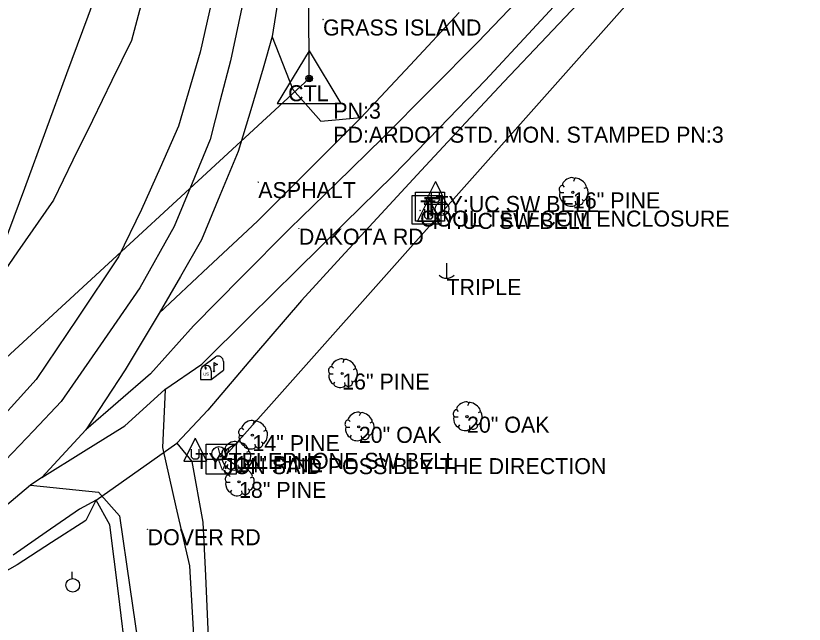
# Model space of a CAD drawing. Extents: x 1404740 to 1407214, y 1837339 to 1847120.
# Drawn here: x 1405702.8 to 1405948.8, y 1842254 to 1842443.8 of the extents above; entities that cross this region are included whole.
import ezdxf

# ---------------------------------------------------------------- set-up
doc = ezdxf.new("R2010")
doc.units = 0
for name, color, linetype in [('Ex_Major Contours', 7, 'Continuous'), ('S_BASELINE', 7, 'Continuous'), ('S_DITCHLINE', 7, 'Continuous'), ('S_EDGE_PAVEMENT', 7, 'Continuous'), ('S_GRAVEL_ROAD', 7, 'Continuous'), ('S_GUARDRAIL', 7, 'Continuous'), ('S_MAILBOX', 7, 'Continuous'), ('S_PAVEMENT_CROWN', 7, 'Continuous'), ('S_RDW_PT_SYM', 7, 'Continuous'), ('S_SECONDARY_CTL', 7, 'Continuous'), ('S_STREAM', 7, 'Continuous'), ('S_SURVEY_TEXT_ANNOT', 7, 'Continuous'), ('S_TELEPHONE_UTILITIES', 7, 'Continuous'), ('S_TREE', 7, 'Continuous'), ('S_TREE_ANNOT', 7, 'Continuous'), ('S_UNDERGROUND_CABLE', 7, 'Continuous'), ('S_UTILITY_POLE', 7, 'Continuous'), ('S_UTILITY_POLE_ANNOT', 7, 'Continuous'), ('S_UTL_PT_SYM', 7, 'Continuous'), ('S_WATER_UTILITIES', 7, 'Continuous'), ('S_WATER_UTILITIES_ANNOT', 7, 'Continuous')]:
    doc.layers.add(name, color=color, linetype=linetype)

msp = doc.modelspace()

# ---------------------------------------------------------------- linework, layer by layer
at = {"layer": 'Ex_Major Contours'}
msp.add_line((1405727.91, 1842292.7), (1405753.09, 1842310.52), dxfattribs=at)
at = {"layer": 'S_BASELINE'}
for p, q in [((1405794.37, 1842424.22), (1405791.52, 1843193.27)), ((1405509.79, 1842162.33), (1405794.37, 1842424.22))]:
    msp.add_line(p, q, dxfattribs=at)
at = {"layer": 'S_DITCHLINE'}
for points in [[(1405881.86, 1842451.53), (1405868.49, 1842437.35), (1405855.12, 1842423.17), (1405841.75, 1842408.98), (1405829.3, 1842395.5), (1405816.85, 1842382.01), (1405804.39, 1842368.53), (1405791.94, 1842355.04), (1405777.34, 1842337.89), (1405762.73, 1842320.75), (1405753.09, 1842310.52), (1405757.74, 1842304.75), (1405761.2, 1842285.84), (1405761.98, 1842269.07), (1405762.76, 1842252.3), (1405763.21, 1842237.38), (1405763.67, 1842222.46), (1405764.12, 1842207.55), (1405764.58, 1842192.63), (1405764.82, 1842178.84), (1405765.06, 1842165.05), (1405765.3, 1842151.25), (1405765.54, 1842137.46)], [(1405727.93, 1842292.76), (1405724.62, 1842286.36), (1405713.94, 1842279.47), (1405703.25, 1842272.57), (1405689.54, 1842264.87), (1405675.82, 1842257.16)], [(1405741, 1842131.76), (1405740.64, 1842146.6), (1405740.27, 1842161.44), (1405739.91, 1842176.28), (1405739.54, 1842191.12), (1405739.02, 1842203.87), (1405738.5, 1842216.62), (1405737.98, 1842229.38), (1405737.46, 1842242.13), (1405734.81, 1842263.59), (1405732.17, 1842285.05), (1405727.91, 1842292.7), (1405722.72, 1842289.93), (1405712.33, 1842282.74), (1405701.94, 1842275.54)]]:
    msp.add_lwpolyline(points, dxfattribs=at)
at = {"layer": 'S_EDGE_PAVEMENT'}
for points in [[(1405710.98, 1842299.77), (1405723.88, 1842307.83), (1405736.78, 1842315.88), (1405749.32, 1842327.2), (1405760.86, 1842335.14), (1405775.63, 1842349.74), (1405790.4, 1842364.34), (1405805.41, 1842379.1), (1405820.42, 1842393.87), (1405834.89, 1842408.8), (1405849.36, 1842423.73), (1405864, 1842439.51), (1405878.64, 1842455.29)], [(1405764.69, 1842451.92), (1405760.37, 1842432.46), (1405753.6, 1842409.33), (1405747.83, 1842396.33), (1405742.06, 1842383.33), (1405734.83, 1842368.65), (1405722.01, 1842349.47), (1405709.18, 1842330.3), (1405692.47, 1842312.03), (1405678.38, 1842299.61), (1405664.29, 1842287.19), (1405647.17, 1842275.28), (1405630.05, 1842263.37), (1405611.25, 1842251.51), (1405592.46, 1842239.65), (1405573.96, 1842228.7), (1405555.46, 1842217.75), (1405536.32, 1842206.98), (1405517.17, 1842196.2), (1405496.28, 1842183.85), (1405477.88, 1842173.74)], [(1405785.18, 1842452.58), (1405782.76, 1842437.37), (1405780.04, 1842427.45), (1405776.11, 1842414.48), (1405772.19, 1842401.51), (1405766.48, 1842387.73), (1405760.77, 1842373.95), (1405754.15, 1842362.5), (1405747.52, 1842351.05), (1405736.91, 1842333.36), (1405724.63, 1842314.65), (1405710.98, 1842299.77), (1405707.4, 1842297.35), (1405691.29, 1842283.83)], [(1405747.52, 1842351.05), (1405762.85, 1842365.38), (1405778.19, 1842379.72), (1405794.34, 1842395.85), (1405810.5, 1842411.98), (1405825.85, 1842428.4), (1405841.19, 1842444.82)], [(1405782.85, 1842437.26), (1405789.25, 1842420.8), (1405797.95, 1842410.9), (1405810.43, 1842412.04)]]:
    msp.add_lwpolyline(points, dxfattribs=at)
at = {"layer": 'S_GRAVEL_ROAD'}
for points in [[(1405749.39, 1842327.13), (1405748.57, 1842309.09), (1405752.79, 1842290.65), (1405757.02, 1842272.21), (1405758.2, 1842252.33), (1405759.38, 1842232.45), (1405760.37, 1842210.37), (1405761.35, 1842188.29), (1405761.66, 1842174.26), (1405761.97, 1842160.22), (1405762.29, 1842146.18), (1405762.6, 1842132.14)], [(1405707.43, 1842297.37), (1405728.64, 1842295.23), (1405735.16, 1842287.82), (1405738.4, 1842265.59), (1405741.63, 1842243.36), (1405741.5, 1842221.53), (1405741.37, 1842199.7), (1405742.7, 1842176.69), (1405744.04, 1842153.69), (1405744.69, 1842140.47), (1405745.35, 1842127.24)]]:
    msp.add_lwpolyline(points, dxfattribs=at)
at = {"layer": 'S_GUARDRAIL'}
for p, q in [((1405794.37, 1842432.92), (1405784.34, 1842416.41)), ((1405794.37, 1842432.92), (1405804.2, 1842416.41)), ((1405784.34, 1842416.41), (1405804.2, 1842416.41))]:
    msp.add_line(p, q, dxfattribs=at)
for radius in [1.04, 0.609, 0.344]:
    msp.add_circle((1405794.37, 1842424.22), radius, dxfattribs=at)
at = {"layer": 'S_MAILBOX'}
for p, q in [((1405761.03, 1842334.35), (1405765.17, 1842337.46)), ((1405764.65, 1842335.64), (1405764.65, 1842332.93)), ((1405767.6, 1842335.99), (1405767.6, 1842333.27)), ((1405760.48, 1842333.08), (1405760.48, 1842330.36)), ((1405763.8, 1842330.36), (1405767.6, 1842333.27)), ((1405763.8, 1842333.08), (1405763.8, 1842330.36)), ((1405760.48, 1842330.36), (1405763.8, 1842330.36))]:
    msp.add_line(p, q, dxfattribs=at)
for points in [[(1405764.65, 1842335.64), (1405765.76, 1842334.98), (1405764.65, 1842334.63)], [(1405761.66, 1842334.19), (1405761.88, 1842334.06), (1405761.88, 1842333.67), (1405762.19, 1842333.67), (1405762.19, 1842334.03), (1405762, 1842334.28), (1405761.66, 1842334.22)]]:
    msp.add_lwpolyline(points, dxfattribs=at)
for centre, end in [((1405765.94, 1842335.99), 117.5718), ((1405762.14, 1842333.08), 180)]:
    msp.add_arc(centre, 1.66, 0, end, dxfattribs=at)
msp.add_ellipse((1405764.65, 1842332.93), major_axis=(0.145, 0.132), ratio=0.564646, dxfattribs=at)
at = {"layer": 'S_PAVEMENT_CROWN'}
for points in [[(1405861.34, 1842450.66), (1405847.12, 1842435.69), (1405832.25, 1842420.71), (1405817.37, 1842405.73), (1405802.84, 1842391.57), (1405788.31, 1842377.4), (1405773.26, 1842362.24), (1405758.22, 1842347.07), (1405744.83, 1842332.11), (1405734.72, 1842323.37), (1405724.61, 1842314.63)], [(1405774.12, 1842449.95), (1405769.82, 1842429.74), (1405766.63, 1842417.47), (1405763.44, 1842405.19), (1405757.82, 1842391.64), (1405752.21, 1842378.08), (1405741.46, 1842358.89), (1405729.24, 1842341.2), (1405717.01, 1842323.51), (1405708.32, 1842314.32), (1405699.63, 1842305.14), (1405685.02, 1842291.71), (1405670.4, 1842278.28), (1405652.86, 1842266.2), (1405635.32, 1842254.13), (1405616.59, 1842242.31), (1405597.85, 1842230.49), (1405579.31, 1842220.01), (1405560.77, 1842209.52), (1405541.46, 1842198.1), (1405522.15, 1842186.68), (1405501.74, 1842174.94), (1405482.15, 1842164.47)]]:
    msp.add_lwpolyline(points, dxfattribs=at)
at = {"layer": 'S_RDW_PT_SYM'}
for points in [[(1405798.69, 1842442.66), (1405798.69, 1842442.71), (1405798.69, 1842442.66), (1405798.64, 1842442.66), (1405798.69, 1842442.66), (1405798.69, 1842442.61), (1405798.69, 1842442.66), (1405798.74, 1842442.66)], [(1405778.46, 1842391.93), (1405778.46, 1842391.98), (1405778.46, 1842391.93), (1405778.41, 1842391.93), (1405778.46, 1842391.93), (1405778.46, 1842391.88), (1405778.46, 1842391.93), (1405778.51, 1842391.93)], [(1405828.96, 1842383.04), (1405828.96, 1842383.09), (1405828.96, 1842383.04), (1405828.91, 1842383.04), (1405828.96, 1842383.04), (1405828.96, 1842382.99), (1405828.96, 1842383.04), (1405829.01, 1842383.04)], [(1405791.13, 1842377.4), (1405791.13, 1842377.45), (1405791.13, 1842377.4), (1405791.08, 1842377.4), (1405791.13, 1842377.4), (1405791.13, 1842377.35), (1405791.13, 1842377.4), (1405791.18, 1842377.4)], [(1405743.94, 1842283.64), (1405743.94, 1842283.69), (1405743.94, 1842283.64), (1405743.89, 1842283.64), (1405743.94, 1842283.64), (1405743.94, 1842283.59), (1405743.94, 1842283.64), (1405743.99, 1842283.64)]]:
    msp.add_lwpolyline(points, dxfattribs=at)
at = {"layer": 'S_STREAM'}
msp.add_lwpolyline([(1405742.27, 1842448.62), (1405738.86, 1842436.09), (1405732.79, 1842423.64), (1405726.71, 1842411.19), (1405720.63, 1842398.74), (1405714.55, 1842386.29), (1405703.36, 1842370.18), (1405692.18, 1842354.08), (1405681.37, 1842343), (1405670.56, 1842331.93), (1405659.74, 1842320.85), (1405648.93, 1842309.77), (1405635.48, 1842298.35), (1405622.03, 1842286.92), (1405608.57, 1842275.5), (1405595.12, 1842264.08), (1405575.38, 1842253.32), (1405555.64, 1842242.57), (1405535.9, 1842231.81), (1405516.16, 1842221.06), (1405504.88, 1842215.38), (1405493.6, 1842209.71), (1405482.32, 1842204.04)], dxfattribs=at)
at = {"layer": 'S_TELEPHONE_UTILITIES'}
for points in [[(1405826.46, 1842378.78), (1405826.46, 1842387.78), (1405835.46, 1842387.78), (1405835.46, 1842378.78)], [(1405827.54, 1842379.74), (1405827.54, 1842388.74), (1405836.54, 1842388.74), (1405836.54, 1842379.74)]]:
    msp.add_lwpolyline(points, close=True, dxfattribs=at)
at = {"layer": 'S_TREE'}
for p, q in [((1405877.2, 1842392.97), (1405876.81, 1842392.12)), ((1405873.4, 1842390.96), (1405873.9, 1842390.37)), ((1405880.76, 1842390.18), (1405880.1, 1842389.91)), ((1405872.74, 1842388.63), (1405873.86, 1842388.63)), ((1405879.99, 1842386.07), (1405879.52, 1842386.5)), ((1405873.9, 1842385.45), (1405874.37, 1842386.15)), ((1405877.58, 1842385.18), (1405877.51, 1842385.96)), ((1405805.19, 1842336.45), (1405804.81, 1842335.59)), ((1405801.4, 1842334.43), (1405801.9, 1842333.85)), ((1405808.76, 1842333.66), (1405808.1, 1842333.38)), ((1405800.74, 1842332.11), (1405801.86, 1842332.11)), ((1405807.98, 1842329.55), (1405807.52, 1842329.97)), ((1405801.9, 1842328.93), (1405802.37, 1842329.63)), ((1405805.58, 1842328.66), (1405805.5, 1842329.43)), ((1405844.15, 1842323), (1405843.76, 1842322.15)), ((1405840.35, 1842320.98), (1405840.85, 1842320.4)), ((1405847.71, 1842320.21), (1405847.05, 1842319.94)), ((1405806.59, 1842317.81), (1405807.1, 1842317.23)), ((1405810.39, 1842319.83), (1405810, 1842318.97)), ((1405839.69, 1842318.66), (1405840.82, 1842318.66)), ((1405773.39, 1842315.22), (1405773.89, 1842314.64)), ((1405777.18, 1842317.24), (1405776.8, 1842316.38)), ((1405805.93, 1842315.49), (1405807.06, 1842315.49)), ((1405813.96, 1842317.04), (1405813.3, 1842316.76)), ((1405840.85, 1842315.48), (1405841.32, 1842316.18)), ((1405844.54, 1842315.21), (1405844.46, 1842315.99)), ((1405846.94, 1842316.1), (1405846.47, 1842316.53)), ((1405772.73, 1842312.9), (1405773.85, 1842312.9)), ((1405780.75, 1842314.45), (1405780.09, 1842314.17)), ((1405807.1, 1842312.31), (1405807.56, 1842313.01)), ((1405810.78, 1842312.04), (1405810.7, 1842312.81)), ((1405813.18, 1842312.93), (1405812.72, 1842313.35)), ((1405771.91, 1842310.68), (1405771.53, 1842309.83)), ((1405773.89, 1842309.72), (1405774.36, 1842310.42)), ((1405777.57, 1842309.45), (1405777.49, 1842310.22)), ((1405779.97, 1842310.34), (1405779.51, 1842310.76)), ((1405768.12, 1842308.66), (1405768.62, 1842308.08)), ((1405775.48, 1842307.89), (1405774.82, 1842307.62)), ((1405767.46, 1842306.34), (1405768.58, 1842306.34)), ((1405768.62, 1842303.16), (1405769.08, 1842303.86)), ((1405772.3, 1842302.89), (1405772.22, 1842303.67)), ((1405774.7, 1842303.78), (1405774.24, 1842304.21)), ((1405769.22, 1842300.64), (1405769.72, 1842300.06)), ((1405773.01, 1842302.66), (1405772.63, 1842301.81)), ((1405768.56, 1842298.32), (1405769.68, 1842298.32)), ((1405776.58, 1842299.87), (1405775.92, 1842299.6)), ((1405769.72, 1842295.14), (1405770.19, 1842295.84)), ((1405773.4, 1842294.87), (1405773.32, 1842295.65)), ((1405775.8, 1842295.76), (1405775.34, 1842296.19))]:
    msp.add_line(p, q, dxfattribs=at)
msp.add_lwpolyline([(1405731.84, 1842461.45), (1405725.25, 1842443.57), (1405718.65, 1842425.68), (1405712.06, 1842407.8), (1405705.47, 1842389.92), (1405698.87, 1842372.03), (1405692.28, 1842354.15), (1405680.14, 1842342.9), (1405668.01, 1842331.65), (1405655.87, 1842320.4), (1405643.74, 1842309.15), (1405631.61, 1842297.9), (1405619.47, 1842286.65), (1405607.34, 1842275.4), (1405595.21, 1842264.15), (1405582.18, 1842257.17), (1405569.16, 1842250.19), (1405556.14, 1842243.21), (1405543.12, 1842236.22), (1405530.09, 1842229.24), (1405517.07, 1842222.26), (1405504.05, 1842215.28), (1405491.03, 1842208.3), (1405470.85, 1842200.65)], dxfattribs=at)
for centre in [(1405876.64, 1842388.73), (1405804.64, 1842332.2), (1405843.59, 1842318.75), (1405809.83, 1842315.58), (1405776.63, 1842312.99), (1405771.36, 1842306.43), (1405772.46, 1842298.41)]:
    msp.add_circle(centre, 0.341, dxfattribs=at)
for centre, major_axis, ratio, start_param, end_param in [((1405875.3, 1842391.93), (1.86, 1.08), 0.471018, 0, 3.141593), ((1405878.96, 1842391.6), (-1.81, 1.36), 0.405113, 3.141593, 6.283186), ((1405873.07, 1842389.81), (0.31, 1.03), 0.646762, 0, 3.141593), ((1405880.31, 1842388.2), (0.46, 2.04), 0.482994, 3.141593, 6.283185), ((1405873.37, 1842387.16), (-0.61, 1.6), 0.420543, 6.283185, 9.424777), ((1405875.83, 1842385.38), (-1.83, 0.19), 0.529943, 0, 3.141593), ((1405878.79, 1842385.67), (1.09, 0.46), 0.711534, 3.141592, 6.283185), ((1405803.3, 1842335.4), (1.86, 1.08), 0.471018, 0, 3.141593), ((1405806.95, 1842335.08), (-1.81, 1.36), 0.405113, 3.141593, 6.283186), ((1405801.07, 1842333.29), (0.31, 1.03), 0.646762, 0, 3.141593), ((1405808.31, 1842331.67), (0.46, 2.04), 0.482994, 3.141593, 6.283185), ((1405801.37, 1842330.64), (-0.61, 1.6), 0.420543, 6.283185, 9.424777), ((1405803.83, 1842328.86), (-1.83, 0.19), 0.529943, 0, 3.141593), ((1405806.79, 1842329.15), (1.09, 0.46), 0.711534, 3.141592, 6.283185), ((1405842.25, 1842321.96), (1.86, 1.08), 0.471018, 0, 3.141593), ((1405845.91, 1842321.63), (-1.81, 1.36), 0.405113, 3.141593, 6.283186), ((1405808.5, 1842318.78), (1.86, 1.08), 0.471018, 0, 3.141593), ((1405812.15, 1842318.46), (-1.81, 1.36), 0.405113, 3.141593, 6.283186), ((1405840.02, 1842319.84), (0.31, 1.03), 0.646762, 0, 3.141593), ((1405847.26, 1842318.22), (0.46, 2.04), 0.482994, 3.141593, 6.283185), ((1405775.29, 1842316.19), (1.86, 1.08), 0.471018, 0, 3.141593), ((1405778.95, 1842315.87), (-1.81, 1.36), 0.405113, 3.141593, 6.283186), ((1405806.26, 1842316.67), (0.31, 1.03), 0.646762, 0, 3.141593), ((1405840.32, 1842317.19), (-0.61, 1.6), 0.420543, 6.283185, 9.424777), ((1405773.06, 1842314.08), (0.31, 1.03), 0.646762, 0, 3.141593), ((1405806.57, 1842314.02), (-0.61, 1.6), 0.420543, 6.283185, 9.424777), ((1405813.51, 1842315.05), (0.46, 2.04), 0.482994, 3.141593, 6.283185), ((1405842.78, 1842315.41), (-1.83, 0.19), 0.529943, 0, 3.141593), ((1405845.74, 1842315.7), (1.09, 0.46), 0.711534, 3.141592, 6.283185), ((1405773.36, 1842311.43), (-0.61, 1.6), 0.420543, 6.283185, 9.424777), ((1405780.3, 1842312.46), (0.46, 2.04), 0.482994, 3.141593, 6.283185), ((1405811.98, 1842312.53), (1.09, 0.46), 0.711534, 3.141592, 6.283185), ((1405770.02, 1842309.64), (1.86, 1.08), 0.471018, 0, 3.141593), ((1405773.67, 1842309.31), (-1.81, 1.36), 0.405113, 3.141593, 6.283186), ((1405778.78, 1842309.94), (1.09, 0.46), 0.711534, 3.141592, 6.283185), ((1405809.03, 1842312.24), (-1.83, 0.19), 0.529943, 0, 3.141593), ((1405767.78, 1842307.52), (0.31, 1.03), 0.646762, 0, 3.141593), ((1405775.82, 1842309.65), (-1.83, 0.19), 0.529943, 0, 3.141593), ((1405775.03, 1842305.9), (0.46, 2.04), 0.482994, 3.141593, 6.283185), ((1405768.09, 1842304.87), (-0.61, 1.6), 0.420543, 6.283185, 9.424777), ((1405770.55, 1842303.09), (-1.83, 0.19), 0.529943, 0, 3.141593), ((1405771.12, 1842301.62), (1.86, 1.08), 0.471018, 0, 3.141593), ((1405773.51, 1842303.38), (1.09, 0.46), 0.711534, 3.141592, 6.283185), ((1405774.77, 1842301.29), (-1.81, 1.36), 0.405113, 3.141593, 6.283186), ((1405768.89, 1842299.5), (0.31, 1.03), 0.646762, 0, 3.141593), ((1405769.19, 1842296.85), (-0.61, 1.6), 0.420543, 6.283185, 9.424777), ((1405776.13, 1842297.88), (0.46, 2.04), 0.482994, 3.141593, 6.283185), ((1405774.61, 1842295.36), (1.09, 0.46), 0.711534, 3.141592, 6.283185), ((1405771.65, 1842295.07), (-1.83, 0.19), 0.529943, 0, 3.141593)]:
    msp.add_ellipse(centre, major_axis=major_axis, ratio=ratio, start_param=start_param, end_param=end_param, dxfattribs=at)
at = {"layer": 'S_UNDERGROUND_CABLE'}
for p, q in [((1405833.77, 1842392.12), (1405830.24, 1842385.03)), ((1405833.77, 1842392.12), (1405837.25, 1842385.03)), ((1405831.65, 1842386.86), (1405828.12, 1842379.76)), ((1405831.65, 1842386.86), (1405835.14, 1842379.76)), ((1405832.57, 1842386.27), (1405832.57, 1842388.71)), ((1405834.93, 1842388.71), (1405834.93, 1842386.27)), ((1405830.24, 1842385.03), (1405837.25, 1842385.03)), ((1405833.19, 1842385.61), (1405832.57, 1842386.27)), ((1405834.39, 1842385.61), (1405833.19, 1842385.61)), ((1405834.93, 1842386.27), (1405834.39, 1842385.61)), ((1405830.45, 1842381), (1405830.45, 1842383.45)), ((1405832.81, 1842383.45), (1405832.81, 1842381)), ((1405828.12, 1842379.76), (1405835.14, 1842379.76)), ((1405831.07, 1842380.35), (1405830.45, 1842381)), ((1405832.27, 1842380.35), (1405831.07, 1842380.35)), ((1405832.81, 1842381), (1405832.27, 1842380.35)), ((1405758.81, 1842311.99), (1405755.28, 1842304.9)), ((1405758.81, 1842311.99), (1405762.29, 1842304.9)), ((1405757.61, 1842306.14), (1405757.61, 1842308.58)), ((1405759.97, 1842308.58), (1405759.97, 1842306.14)), ((1405758.23, 1842305.48), (1405757.61, 1842306.14)), ((1405759.43, 1842305.48), (1405758.23, 1842305.48)), ((1405759.97, 1842306.14), (1405759.43, 1842305.48)), ((1405755.28, 1842304.9), (1405762.29, 1842304.9))]:
    msp.add_line(p, q, dxfattribs=at)
at = {"layer": 'S_UTILITY_POLE'}
for p, q in [((1405835.71, 1842385.76), (1405835.71, 1842387.87)), ((1405837.17, 1842366.63), (1405837.17, 1842361.9)), ((1405720.44, 1842268.29), (1405720.44, 1842270.39))]:
    msp.add_line(p, q, dxfattribs=at)
for centre in [(1405835.83, 1842383.62), (1405720.57, 1842266.14)]:
    msp.add_circle(centre, 2.13, dxfattribs=at)
msp.add_arc((1405837.23, 1842365.32), 3.41, 226.3972, 313.6028, dxfattribs=at)
at = {"layer": 'S_UTL_PT_SYM'}
msp.add_lwpolyline([(1405767.47, 1842305.82), (1405767.47, 1842305.87), (1405767.47, 1842305.82), (1405767.42, 1842305.82), (1405767.47, 1842305.82), (1405767.47, 1842305.77), (1405767.47, 1842305.82), (1405767.52, 1842305.82)], dxfattribs=at)
at = {"layer": 'S_WATER_UTILITIES'}
for p, q in [((1405948.84, 1842509.73), (1405767.47, 1842305.82)), ((1405762.2, 1842310.18), (1405771.62, 1842310.18)), ((1405762.2, 1842300.77), (1405762.2, 1842310.18)), ((1405768.1, 1842308.32), (1405770.93, 1842310.05)), ((1405771.62, 1842310.18), (1405771.62, 1842300.77)), ((1405762.2, 1842305.5), (1405771.62, 1842305.5)), ((1405767.98, 1842306.01), (1405770.89, 1842304.08)), ((1405771.62, 1842300.77), (1405762.2, 1842300.77))]:
    msp.add_line(p, q, dxfattribs=at)
msp.add_circle((1405766.2, 1842307.26), 2.18, dxfattribs=at)

# ---------------------------------------------------------------- texts
at = {"layer": 'S_GUARDRAIL'}
msp.add_text('CTL', height=5, rotation=360, dxfattribs=at).set_placement((1405787.79, 1842417.15))
for s, p in [('PN:3', (1405801.87, 1842411.72)), ('PD:ARDOT STD. MON. STAMPED PN:3', (1405801.87, 1842404.22))]:
    msp.add_text(s, height=5, dxfattribs=at).set_placement(p)
at = {"layer": 'S_MAILBOX'}
msp.add_text('US', height=0.96, rotation=360, dxfattribs=at).set_placement((1405761.24, 1842331.56))
at = {"layer": 'S_SECONDARY_CTL'}
msp.add_text('COOL TELECOM ENCLOSURE', height=5, dxfattribs=at).set_placement((1405828.96, 1842378.04))
at = {"layer": 'S_SURVEY_TEXT_ANNOT'}
for s, p in [('GRASS ISLAND', (1405798.69, 1842437.66)), ('ASPHALT', (1405778.46, 1842386.93)), ('DAKOTA RD', (1405791.13, 1842372.4)), ('DOVER RD', (1405743.94, 1842278.64))]:
    msp.add_text(s, height=5, dxfattribs=at).set_placement(p)
at = {"layer": 'S_TELEPHONE_UTILITIES'}
for p in [(1405830.1, 1842381.24), (1405829.02, 1842380.28)]:
    msp.add_text('T', height=6, rotation=360, dxfattribs=at).set_placement(p)
at = {"layer": 'S_TREE_ANNOT'}
for s, p in [('16" PINE', (1405876.64, 1842383.73)), ('16" PINE', (1405804.64, 1842327.2)), ('20" OAK', (1405843.59, 1842313.75)), ('20" OAK', (1405809.83, 1842310.58)), ('14" PINE', (1405776.63, 1842307.99)), ('14" PINE', (1405771.36, 1842301.43)), ('18" PINE', (1405772.46, 1842293.41))]:
    msp.add_text(s, height=5, dxfattribs=at).set_placement(p)
at = {"layer": 'S_UTILITY_POLE_ANNOT'}
for s, p in [('TY:UC SW BELL', (1405833.77, 1842382.59)), ('TY:UC SW BELL', (1405831.65, 1842377.32)), ('TRIPLE', (1405837.18, 1842356.68)), ('TY:TELEPHONE SW BELL', (1405758.81, 1842302.46))]:
    msp.add_text(s, height=5, dxfattribs=at).set_placement(p)
at = {"layer": 'S_WATER_UTILITIES'}
for s, p in [('W', (1405765.75, 1842306.03)), ('V', (1405765.99, 1842301.96))]:
    msp.add_text(s, height=3, rotation=360, dxfattribs=at).set_placement(p)
at = {"layer": 'S_WATER_UTILITIES_ANNOT'}
msp.add_text('JON SAID POSSIBLY THE DIRECTION', height=5, dxfattribs=at).set_placement((1405767.47, 1842300.82))

doc.saveas('drawing.dxf')
